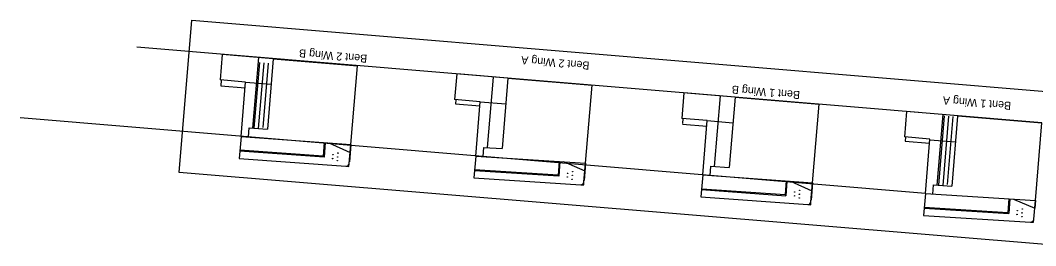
# Model space of a CAD drawing. Extents: x 1313815 to 1314857, y 2089008 to 2089414.
# Drawn here: x 1314329.2 to 1314467.6, y 2089210.1 to 2089240.8 of the extents above; entities that cross this region are included whole.
import ezdxf

# ---------------------------------------------------------------- set-up
doc = ezdxf.new("R2010")
doc.units = 0
for name, color, linetype in [('B-Gen-Construction Line', 7, 'Continuous'), ('B-Gen-Hidden', 7, 'Continuous'), ('B-Gen-Rebar', 7, 'Continuous'), ('B-Gen-Rebar (1)', 7, 'Continuous'), ('B-Gen-Viewport', 7, 'Continuous'), ('B-Sub-Abutment Cap (Hidden)', 7, 'Continuous'), ('B-Sub-Wingwall', 7, 'Continuous'), ('B-Super-Parapet', 7, 'Continuous')]:
    doc.layers.add(name, color=color, linetype=linetype)

msp = doc.modelspace()

# ---------------------------------------------------------------- linework, layer by layer
at = {"layer": 'B-Gen-Construction Line'}
for p, q in [((1314468.41, 2089226.85), (1314345.04, 2089237.15)), ((1314452.55, 2089217.2), (1314329.18, 2089227.5))]:
    msp.add_line(p, q, dxfattribs=at)
at = {"layer": 'B-Gen-Hidden'}
for p, q in [((1314363.66, 2089235.58), (1314362.86, 2089225.99)), ((1314395.65, 2089232.91), (1314394.85, 2089223.34)), ((1314426.6, 2089230.34), (1314425.8, 2089220.74)), ((1314456.94, 2089227.73), (1314456.15, 2089218.23)), ((1314360.26, 2089224.91), (1314360.37, 2089226.17)), ((1314360.37, 2089226.17), (1314362.86, 2089225.99)), ((1314359.27, 2089224.98), (1314374.23, 2089223.89)), ((1314370.61, 2089224.15), (1314370.47, 2089222.28)), ((1314370.74, 2089224.15), (1314370.59, 2089222.15)), ((1314370.59, 2089222.15), (1314359.1, 2089222.99)), ((1314370.47, 2089222.28), (1314359.11, 2089223.12)), ((1314371.23, 2089224.11), (1314374.14, 2089222.81)), ((1314392.25, 2089222.25), (1314392.35, 2089223.5)), ((1314392.35, 2089223.5), (1314394.85, 2089223.34)), ((1314391.25, 2089222.31), (1314406.22, 2089221.36)), ((1314402.61, 2089221.59), (1314402.49, 2089219.72)), ((1314402.73, 2089221.59), (1314402.6, 2089219.59)), ((1314403.23, 2089221.55), (1314406.13, 2089220.28)), ((1314373.57, 2089220.93), (1314373.98, 2089220.9)), ((1314373.98, 2089220.9), (1314374.01, 2089221.31)), ((1314402.6, 2089219.59), (1314391.09, 2089220.32)), ((1314402.49, 2089219.72), (1314391.1, 2089220.45)), ((1314423.2, 2089219.66), (1314423.3, 2089220.92)), ((1314423.2, 2089219.67), (1314423.3, 2089220.9)), ((1314423.3, 2089220.92), (1314425.8, 2089220.74)), ((1314405.98, 2089218.37), (1314406.01, 2089218.78)), ((1314422.2, 2089219.73), (1314437.16, 2089218.66)), ((1314433.55, 2089218.92), (1314433.42, 2089217.05)), ((1314433.68, 2089218.91), (1314433.53, 2089216.91)), ((1314434.17, 2089218.87), (1314437.07, 2089217.58)), ((1314405.57, 2089218.4), (1314405.98, 2089218.37)), ((1314422.04, 2089217.74), (1314433.53, 2089216.91)), ((1314422.05, 2089217.86), (1314433.42, 2089217.05)), ((1314452.55, 2089217.2), (1314467.53, 2089216.27)), ((1314453.55, 2089217.14), (1314453.65, 2089218.38)), ((1314453.55, 2089217.14), (1314453.65, 2089218.37)), ((1314453.65, 2089218.38), (1314456.15, 2089218.23)), ((1314436.92, 2089215.67), (1314436.95, 2089216.08)), ((1314463.91, 2089216.49), (1314463.79, 2089214.62)), ((1314464.03, 2089216.49), (1314463.91, 2089214.49)), ((1314464.53, 2089216.45), (1314467.44, 2089215.19)), ((1314436.51, 2089215.7), (1314436.92, 2089215.67)), ((1314452.38, 2089215.2), (1314463.91, 2089214.49)), ((1314452.39, 2089215.33), (1314463.79, 2089214.62)), ((1314466.87, 2089213.3), (1314467.28, 2089213.28)), ((1314467.28, 2089213.28), (1314467.31, 2089213.69))]:
    msp.add_line(p, q, dxfattribs=at)
at = {"layer": 'B-Gen-Rebar'}
for centre, radius in [((1314372.46, 2089222.71), 0.0312), ((1314371.74, 2089221.97), 0.0313), ((1314371.78, 2089222.49), 0.0313), ((1314372.39, 2089221.67), 0.0313), ((1314372.43, 2089222.19), 0.0313), ((1314403.77, 2089219.97), 0.0313), ((1314404.46, 2089220.19), 0.0312), ((1314403.74, 2089219.45), 0.0313), ((1314404.39, 2089219.15), 0.0313), ((1314404.42, 2089219.67), 0.0313), ((1314434.73, 2089217.41), 0.0313), ((1314435.41, 2089217.63), 0.0312), ((1314434.69, 2089216.89), 0.0313), ((1314435.34, 2089216.59), 0.0313), ((1314435.38, 2089217.11), 0.0313), ((1314465.08, 2089214.87), 0.0313), ((1314465.72, 2089214.57), 0.0313), ((1314465.76, 2089215.09), 0.0312), ((1314465.04, 2089214.35), 0.0313), ((1314465.69, 2089214.05), 0.0313)]:
    msp.add_circle(centre, radius, dxfattribs=at)
at = {"layer": 'B-Gen-Rebar (1)'}
for p, q in [((1314361.07, 2089226.12), (1314361.82, 2089235.08)), ((1314361.66, 2089226.07), (1314362.41, 2089235.03)), ((1314362.26, 2089226.2), (1314362.99, 2089234.98)), ((1314454.36, 2089218.34), (1314455.15, 2089227.79)), ((1314454.95, 2089218.3), (1314455.73, 2089227.74)), ((1314455.55, 2089218.43), (1314456.32, 2089227.69))]:
    msp.add_line(p, q, dxfattribs=at)
at = {"layer": 'B-Gen-Viewport'}
msp.add_lwpolyline([(1314470.54, 2089210.1), (1314350.83, 2089220.09), (1314352.56, 2089240.81), (1314472.27, 2089230.82)], close=True, dxfattribs=at)
at = {"layer": 'B-Sub-Abutment Cap (Hidden)'}
for p, q in [((1314360.87, 2089226.13), (1314361.67, 2089235.75)), ((1314392.85, 2089223.46), (1314393.66, 2089233.08)), ((1314359.88, 2089232.39), (1314363.37, 2089232.1)), ((1314391.87, 2089229.72), (1314395.36, 2089229.43)), ((1314423.8, 2089220.88), (1314424.61, 2089230.51)), ((1314422.82, 2089227.15), (1314426.31, 2089226.86)), ((1314454.15, 2089218.34), (1314454.96, 2089227.98)), ((1314453.16, 2089224.53), (1314456.65, 2089224.24))]:
    msp.add_line(p, q, dxfattribs=at)
at = {"layer": 'B-Sub-Wingwall'}
for p, q in [((1314356.69, 2089236.17), (1314356.4, 2089232.68)), ((1314363.66, 2089235.58), (1314356.69, 2089236.17)), ((1314363.66, 2089235.58), (1314375.12, 2089234.63)), ((1314374.23, 2089223.89), (1314375.12, 2089234.63)), ((1314359.88, 2089232.39), (1314356.4, 2089232.68)), ((1314356.56, 2089232.66), (1314356.5, 2089231.9)), ((1314388.67, 2089233.5), (1314388.38, 2089230.01)), ((1314395.65, 2089232.91), (1314388.67, 2089233.5)), ((1314395.65, 2089232.91), (1314407.11, 2089231.96)), ((1314356.5, 2089231.9), (1314359.82, 2089231.63)), ((1314359.27, 2089224.98), (1314359.88, 2089232.39)), ((1314406.22, 2089221.36), (1314407.11, 2089231.96)), ((1314391.87, 2089229.72), (1314388.38, 2089230.01)), ((1314388.55, 2089229.99), (1314388.5, 2089229.43)), ((1314391.25, 2089222.31), (1314391.87, 2089229.72)), ((1314419.62, 2089230.93), (1314419.33, 2089227.44)), ((1314426.6, 2089230.34), (1314419.62, 2089230.93)), ((1314426.6, 2089230.34), (1314438.06, 2089229.39)), ((1314388.5, 2089229.43), (1314391.82, 2089229.15)), ((1314437.16, 2089218.66), (1314438.06, 2089229.39)), ((1314449.97, 2089228.39), (1314449.68, 2089224.91)), ((1314456.95, 2089227.81), (1314449.97, 2089228.39)), ((1314422.82, 2089227.15), (1314419.33, 2089227.44)), ((1314419.5, 2089227.43), (1314419.44, 2089226.76)), ((1314422.2, 2089219.73), (1314422.82, 2089227.15)), ((1314456.95, 2089227.81), (1314468.41, 2089226.85)), ((1314419.43, 2089226.65), (1314422.76, 2089226.37)), ((1314467.53, 2089216.27), (1314468.41, 2089226.85)), ((1314453.17, 2089224.61), (1314449.68, 2089224.91)), ((1314449.85, 2089224.89), (1314449.8, 2089224.34)), ((1314449.8, 2089224.34), (1314453.12, 2089224.06)), ((1314452.55, 2089217.2), (1314453.17, 2089224.61))]:
    msp.add_line(p, q, dxfattribs=at)
for centre in [(1314373.6, 2089221.35), (1314405.59, 2089218.82), (1314436.53, 2089216.11), (1314466.89, 2089213.72)]:
    msp.add_arc(centre, 0.417, 266.1099, 355.2284, dxfattribs=at)
at = {"layer": 'B-Super-Parapet'}
for p, q in [((1314359.27, 2089224.98), (1314359.02, 2089222)), ((1314374.01, 2089221.31), (1314374.23, 2089223.89)), ((1314374.23, 2089223.89), (1314374.03, 2089221.52)), ((1314359.02, 2089222), (1314373.57, 2089220.93)), ((1314391.25, 2089222.31), (1314391, 2089219.33)), ((1314406.01, 2089218.78), (1314406.22, 2089221.36)), ((1314406.22, 2089221.36), (1314406.03, 2089219)), ((1314391, 2089219.33), (1314405.57, 2089218.4)), ((1314422.2, 2089219.73), (1314421.95, 2089216.74)), ((1314436.95, 2089216.08), (1314437.16, 2089218.66)), ((1314437.16, 2089218.66), (1314436.97, 2089216.29)), ((1314437.16, 2089218.66), (1314437.07, 2089217.58)), ((1314452.55, 2089217.2), (1314452.3, 2089214.21)), ((1314421.95, 2089216.74), (1314436.51, 2089215.7)), ((1314467.31, 2089213.69), (1314467.53, 2089216.27)), ((1314467.53, 2089216.27), (1314467.44, 2089215.19)), ((1314452.3, 2089214.21), (1314466.87, 2089213.3))]:
    msp.add_line(p, q, dxfattribs=at)

# ---------------------------------------------------------------- texts
at = {"layer": 'B-Sub-Abutment Cap (Hidden)'}
for s, p in [('Bent 2 Wing B', (1314376.5, 2089236.1)), ('Bent 2 Wing A', (1314406.79, 2089235.16)), ('Bent 1 Wing B', (1314435.49, 2089231.15)), ('Bent 1 Wing A', (1314464.26, 2089229.68))]:
    msp.add_text(s, height=1.0911, rotation=175.2284, dxfattribs=at).set_placement(p)

doc.saveas('drawing.dxf')
